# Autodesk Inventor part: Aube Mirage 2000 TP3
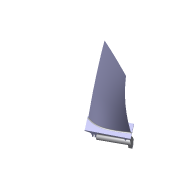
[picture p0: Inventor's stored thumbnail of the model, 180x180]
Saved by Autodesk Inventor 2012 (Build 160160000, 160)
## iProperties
Created: 2012-02
Part Number: Aube Mirage 2000 TP3
Material: Par défaut
Document SubType Name: Modeling
Designer: UnKnown
Density: 1 g/cm^3
Mass: 54.1836 g
Surface Area: 330.112 cm^2
Volume: 54.1836 cm^3
Author: Prof
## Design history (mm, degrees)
node "pale.CATPart1"
node "Plan de construction1"
sketch "Esquisse1"
  geometry: L1 (-21.889, 20.019)-(148.111, 20.019); L2 (148.111, 20.019)-(148.111, -43.964); L3 (148.111, -43.964)-(-21.889, -43.964); L4 (-21.889, -43.964)-(-21.889, 20.019); L5 (0, -29.201)-(0, 9.935) reference; L6 (0, -19.33)-(-20.422, -19.33); L7 (-2.854, -13.903)-(0, -13.903); L8 (-2.854, -24.757)-(0, -24.757); L9 (0, -13.903)-(0, -24.757); L10 (-14.558, -19.33)-(-14.558, -16.286); L11 (-2.854, -24.757)-(0, -24.757); 13 further points; 1 other entity
  constraints: 12 end point, 8 symmetric about line, 3 point on line, 2 horizontal, 2 parallel, 2 perpendicular, 2 vertical, 1 horizontal alignment, 18 other
  dimensions: "d27" = 170 distance between parallel lines of L2 L4
sketch "Esquisse 3D1"
feature "Balayage1" sketch "Esquisse1", "Esquisse 3D1" dims "d45" = 0
fillet "Congé3" dims "d51" = 0.1
fillet "Congé2" dims "d50" = 2
sketch "Esquisse2"
  geometry: L1 (78.476, 0)-(0, 0) reference; L2 (0, 0)-(0, -10) reference; L3 (12, -8.325)-(12, -25.716); L4 (12, -25.716)-(-4.711, -25.716); L5 (-4.711, -25.716)-(-4.711, -1); L6 (-4.711, -1)-(6.713, -2.367); A1 r 6 centre (6, -8.325) between (12, -8.325) and (6.713, -2.367); 2 further points
  constraints: 8 end point, 2 point on circle, 2 tangent, 1 centre point, 1 parallel, 1 point on line
  dimensions: "d53" = 12 distance between parallel lines of L2 L3; "d54" = 3 distance from line of point (12, -3) L1; "d55" = 1 distance from line of L5.end L1; "d56" = 6 radius of A1
sketch "Esquisse 3D2"
feature "Balayage2" sketch "Esquisse2", "Esquisse 3D2" dims "d57" = 0
sketch "Esquisse 3D3"
sketch "Esquisse3"
  geometry: L1 (70.411, -5.013)-(70.411, -5.013); L2 (80.622, -1.346)-(73.14, -2.025); L3 (78.476, -24.557)-(78.477, -24.557); L4 (74.351, -15.565)-(73.405, -13.599); L5 (80.622, -1.346)-(80.622, -28.389); L6 (78.627, -24.413)-(78.328, -23.818); A1 r 3 centre (73.411, -5.013) between (73.14, -2.025) and (70.411, -5.013); A2 r 10000 centre (9084.138, 4323.068) between (73.5, -13.796) and (74.257, -15.369); A3 r 16.374 centre (93.111, -16.77) between (78.36, -23.877) and (78.599, -24.353); 9 further points
  constraints: 12 end point, 5 point on circle, 4 midpoint, 3 centre point, 2 tangent, 1 point on line, 14 other
  dimensions: "d58" = 3 radius of A1
feature "Balayage3" sketch "Esquisse3" dims "d59" = 0
sketch "Esquisse4"
  geometry: L1 (11.888, 10)-(71.306, 10) reference; L2 (11.888, 10)-(11.888, 8.325) reference; L3 (78, 0)-(78, 1.541) reference; L4 (13.888, 10)-(13.888, 6); L5 (16.388, 6)-(16.388, 10); L6 (13.888, 10)-(16.388, 10); A1 r 1.25 centre (15.138, 6) between (13.888, 6) and (16.388, 6); 1 further point
  constraints: 6 end point, 2 parallel, 2 point on circle, 2 point on line, 2 tangent, 1 centre point, 1 collinear
  dimensions: "d63" = 2.5 distance between parallel lines of L5 L4; "d67" = 4 distance of L4.start L4.end; "d69" = 2 distance between parallel lines of L2 L4
sketch "Esquisse 3D4"
feature "Balayage4" sketch "Esquisse4", "Esquisse 3D4" dims "d71" = 0
node "Esquisse 3D5"
sketch "Esquisse5"
  geometry: L1 (0, -13.903)-(0, 0) reference; L2 (0, -5.255)-(-22.353, -5.255); L3 (-22.353, -5.255)-(-22.353, -33.235); L4 (-22.353, -33.235)-(0, -33.235); L5 (0, -33.235)-(0, -5.255); 1 further point
  constraints: 8 end point, 2 parallel, 1 horizontal, 1 perpendicular, 1 point on line
extrude "Extrusion1" cut sketch "Esquisse5" distance "d72" = 10; taper "d73" = 0 deg
sketch "Esquisse6"
  geometry: L1 (16.388, 10)-(71.306, 10) reference; L2 (16.388, 10)-(16.388, 6) reference; L3 (18.388, 10)-(68.008, 10); L4 (68.008, 5.013)-(68.008, 1.541); L5 (68.008, 1.541)-(18.388, 1.541); L6 (18.388, 1.541)-(18.388, 10); L7 (70.008, 5.013)-(68.008, 5.013); 1 further point
  constraints: 10 end point, 2 parallel, 2 perpendicular, 1 horizontal, 1 point on line, 1 other
  dimensions: "d74" = 2 distance from line of L4 L7.start; "d75" = 2 distance between parallel lines of L6 L2
sketch "Esquisse 3D6"
feature "Balayage5" sketch "Esquisse6", "Esquisse 3D6" dims "d76" = 0
sketch "Esquisse7"
  geometry: L1 (16.542, -6)-(16.542, -10) reference; L2 (71.72, -10)-(16.542, -10) reference; L3 (18.542, -10)-(68.411, -10); L4 (68.411, -5.013)-(68.411, -1.564); L5 (68.411, -1.564)-(18.542, -1.564); L6 (18.542, -1.564)-(18.542, -10); L7 (70.411, -5.013)-(68.411, -5.013); 1 further point
  constraints: 10 end point, 2 parallel, 2 perpendicular, 1 horizontal, 1 point on line, 1 other
  dimensions: "d77" = 2 distance from line of L4 L7.start; "d78" = 2 distance between parallel lines of L1 L6
sketch "Esquisse 3D7"
feature "Balayage6" sketch "Esquisse7", "Esquisse 3D7" dims "d79" = 0
fillet "Congé4" dims "d80" = 3
fillet "Congé5" dims "d81" = 6
sketch "Esquisse8"
  geometry: L1 (51.463, -13.53)-(58.463, -13.53); L2 (58.463, -13.53)-(58.463, -20.558); L3 (58.463, -20.558)-(51.463, -20.558); L4 (51.463, -20.558)-(51.463, -13.53); L5 (58.463, -14.558)-(-3.115, -14.558) reference; 1 further point
  constraints: 8 end point, 2 parallel, 1 horizontal, 1 perpendicular
  dimensions: "d82" = 7 distance of L2.end L3.end; "d83" = 6 distance between parallel lines of L3 L5
sketch "Esquisse 3D8"
feature "Balayage7" sketch "Esquisse8", "Esquisse 3D8" dims "d84" = 0
feature "Dépouille de face1" dims angle "d85" = 5 deg
sketch "Esquisse9"
  geometry: L1 (8.948, -7.162)-(-7.647, -7.162); L2 (-7.647, -7.162)-(-7.647, 18.023); L3 (-7.647, 18.023)-(8.948, 18.023); L4 (8.948, 18.023)-(8.948, -7.162); 1 further point
  constraints: 8 end point, 2 parallel, 1 horizontal, 1 perpendicular
extrude "Extrusion2" cut sketch "Esquisse9" distance "d86" = 10; taper "d87" = 0 deg
fillet "Congé6" dims "d88" = 1
fillet "Congé7" dims "d89" = 0.3
fillet "Congé8" dims "d90" = 0.3
fillet "Congé9" dims "d91" = 0.2
fillet "Congé10" dims "d92" = 0.2
fillet "Congé11" dims "d93" = 0.5
fillet "Congé12" dims "d94" = 0.5
fillet "Congé14" dims "d96" = 2
fillet "Congé15" dims "d97" = 0.5
node "PartBody"
node "Base1"
node "Image1"
other parameters: "sa_0" = 1000000
